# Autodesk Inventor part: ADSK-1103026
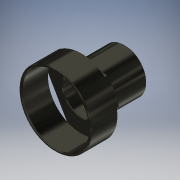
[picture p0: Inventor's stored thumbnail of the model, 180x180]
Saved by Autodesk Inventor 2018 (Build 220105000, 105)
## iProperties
Shininess: 41.0
Length Units: 11272
Angle Units: 11279
Time Units: 11290
Mass Units: 11286
Length Display Precision: 4
Angle Display Precision: 2
Compacted: True
Created: 2000-08
Part Number: ADSK-1103026
Document SubType Name: Modeling
Description: 24 TOOTH CLUTCH GEAR
Mass: 3.13134 g
Surface Area: 23.3651 cm^2
Volume: 1.15548 cm^3
Density: 2.71 g/cm^3
Material: Aluminum-6061
Appearance: Gunmetal
Density: 0.0
Volumn: 0.0
Area: 0.0
PropertySet Name: Model Information
Control State: 0
Master: False
Checked Out: False
Author: Autodesk, Inc.
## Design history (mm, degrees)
node "Extrusion1" dims "d1" = 8.4328, "d2" = 0
  sketch "Sketch3"
    geometry: C1 r 10.477 at (-1.128, -0.122)
    constraints: 1 centre point
    dimensions: "d0" = 20.955 diameter of C1
node "Shell1" dims "d3" = 0.8128
node "Extrusion2" dims "d5" = 11.8872, "d6" = 0
  sketch "Sketch4"
    geometry: C1 r 10.477 at (0, 0) reference; C2 r 6.35 at (0, 0)
    constraints: 1 centre point, 1 concentric
    dimensions: "d4" = 12.7 diameter of C2
node "Extrusion3" dims "d8" = 0.8128, "d9" = 0
  sketch "Sketch5"
    geometry: L1 (-6.839, 7.938)-(6.839, 7.938); A1 r 10.477 centre (0, 0) between (-6.839, 7.938) and (6.839, 7.938) reference
    constraints: 2 end point, 2 point on circle, 1 horizontal
    dimensions: "d7" = 2.54 distance edge to line of A1 L1
node "Circular Pattern1" dims "d10" = 30, "d12" = 360 deg
node "Extrusion4" dims "d14" = 2.99974, "d15" = 0
  sketch "Sketch6"
    geometry: C1 r 6.35 at (0, 0) reference; C2 r 5.524 at (0, 0)
    constraints: 1 centre point, 1 coincident
    dimensions: "d13" = 11.049 diameter of C2
node "Extrusion5" dims "d16" = 2.99974, "d17" = 0
  sketch "Sketch7"
    geometry: C1 r 5.524 at (5.514, -7.938) reference
node "Extrusion6" dims "d19" = 2.54, "d20" = 0
  sketch "Sketch8"
    geometry: C1 r 5.524 at (0, 0) reference; C2 r 4.255 at (0, 0)
    constraints: 1 centre point, 1 coincident
    dimensions: "d18" = 1.27 radial gap between concentric circles of C1 C2
node "Chamfer1" dims "d21" = 0.254, "d22" = 0.254, "d23" = 45 deg
body "Solid1"
